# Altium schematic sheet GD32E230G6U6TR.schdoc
size 127 x 101 mm
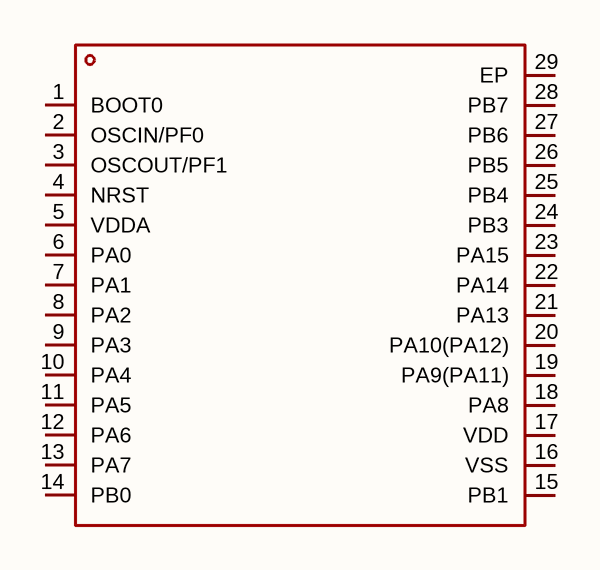
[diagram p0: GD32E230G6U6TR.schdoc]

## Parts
U?  gd32e230g6u6tr  [QFN-28_L4.0-W4.0-P0.40-BL-EP2.8]  (value not drawn)

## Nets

Not connected (* = marked no-connect by the designer): U? 1(BOOT0) 2(OSCIN/PF0) 3(OSCOUT/PF1) 4(NRST) 5(VDDA) 6(PA0) 7(PA1) 8(PA2) 9(PA3) 10(PA4) 11(PA5) 12(PA6) 13(PA7) 14(PB0) 15(PB1) 16(VSS) 17(VDD) 18(PA8) 19(PA9(PA11)) 20(PA10(PA12)) 21(PA13) 22(PA14) 23(PA15) 24(PB3) 25(PB4) 26(PB5) 27(PB6) 28(PB7) 29(EP)

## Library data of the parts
U? = gd32e230g6u6tr: CPU内核:ARM Cortex-M23;CPU最大主频:72MHz;CPU位数:32 Bit;; Manufacturer: GigaDevice(兆易创新); AddInBom: yes; ModelId: ea8b28b44f5d42878c4615c9108a8123; ModelTransform: 157.48,157.48,0,0,0,0,0,0,0; CPU Maximum Speed: 72MHz; Core Size: 32 Bit; Program Storage Size: 32KB; Program Memory Type: FLASH; RAM Size: 6KB; Number of I/O: 23; ADC (Bit): 12bit; Voltage - Supply: 1.8V~3.6V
